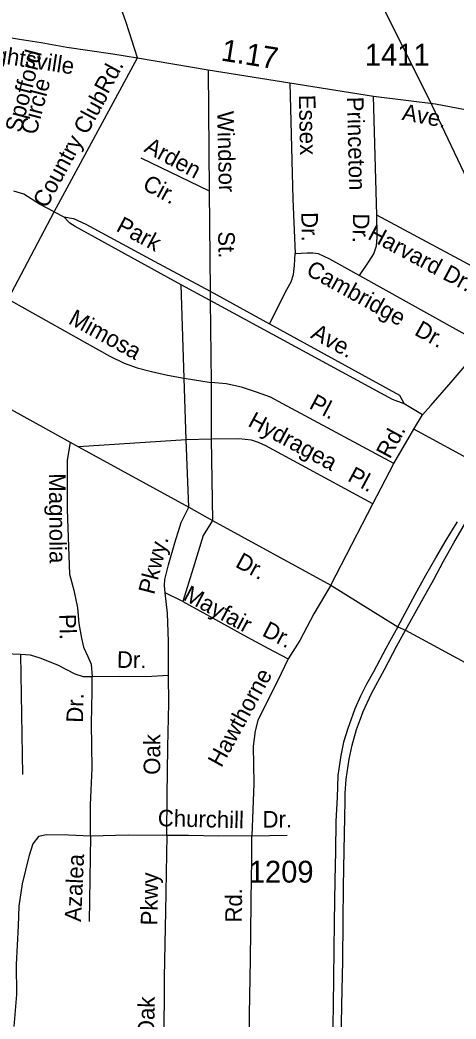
# Model space of a CAD drawing. Extents: x 2290055 to 2389491, y 66597 to 237875.
# Drawn here: x 2328196 to 2330699, y 169694 to 175420 of the extents above; entities that cross this region are included whole.
import ezdxf

# ---------------------------------------------------------------- set-up
doc = ezdxf.new("R2010")
doc.units = 0
for name, color, linetype in [('Exist Road Non-System Type 51', 7, 'Continuous'), ('Exist Road Non-System Type 51 Label', 7, 'Continuous'), ('Exist Road Primary US Label', 7, 'Continuous'), ('Exist Road Primary US UnDivided 4 Lane Attributed', 7, 'Continuous'), ('Exist Road Secondary Mileage Hundredths English Label', 7, 'Continuous'), ('Exist Road Secondary Type 51 Attributed', 7, 'Continuous'), ('Exist Road Secondary Type 51 Divided Attributed', 7, 'Continuous'), ('Exist Road Secondary Type 51 Label', 7, 'Continuous'), ('Exist Road Secondary Type 51 Number Label', 7, 'Continuous')]:
    doc.layers.add(name, color=color, linetype=linetype)

msp = doc.modelspace()

# ---------------------------------------------------------------- linework, layer by layer
at = {"layer": 'Exist Road Non-System Type 51'}
for p, q in [((2330561.4, 174929.9), (2330257.1, 175546)), ((2328392.9, 174319.9), (2328871.9, 175203)), ((2329277, 175135.1), (2329282.6, 174441.1)), ((2330244.3, 174301), (2330225.2, 174982.6)), ((2330818.7, 174392), (2330561.4, 174929.9)), ((2329282.6, 174441.1), (2329287.2, 173865)), ((2328128.5, 173819.2), (2328392.9, 174319.9)), ((2328392.9, 174319.9), (2328447.8, 174291.9)), ((2330822.7, 173991.8), (2330244.3, 174301)), ((2330145.8, 173955.1), (2330814.9, 173583.5)), ((2329287.3, 173813.2), (2329121.6, 173902.4)), ((2329138.9, 173367.2), (2329121.6, 173902.4)), ((2329287.2, 173865), (2329287.3, 173813.2)), ((2329287.2, 173865), (2329628.7, 173678.7)), ((2329287.3, 173813.2), (2329293.7, 173343.1)), ((2329138.9, 173367.2), (2329293.7, 173343.1)), ((2329150.9, 173013.5), (2329138.9, 173367.2)), ((2329293.7, 173343.1), (2329294.8, 173016.9)), ((2330507.6, 173157.2), (2330401, 173220.9)), ((2330456.7, 173075.1), (2330507.6, 173157.2)), ((2330342.7, 172878.6), (2330456.7, 173075.1)), ((2330896.4, 172836.5), (2330456.7, 173075.1)), ((2329150.9, 173013.5), (2328532.2, 172973)), ((2329294.8, 173016.9), (2329150.9, 173013.5)), ((2329166.2, 172627.9), (2329150.9, 173013.5)), ((2329294.8, 173016.9), (2329301.1, 172551.2)), ((2330221.5, 172647.6), (2330342.7, 172878.6)), ((2329980.1, 172179.9), (2330221.5, 172647.6)), ((2329131.5, 172086.3), (2329029.4, 172136.4)), ((2328199.3, 171783.2), (2328210.4, 171095.4)), ((2328600.5, 170741), (2328593.9, 170252.4)), ((2329526.6, 170743.5), (2329730.6, 170747.6))]:
    msp.add_line(p, q, dxfattribs=at)
for points in [[(2328871.9, 175203), (2328806.1, 175406.5), (2328718.2, 175653.2), (2328685.2, 175781.8)], [(2329746, 175059.8), (2329762.6, 174392.2), (2329776.8, 174082.6)], [(2328890.6, 174629.8), (2329282.6, 174441.1)], [(2328392.9, 174319.9), (2328309.1, 174364.5), (2328218.9, 174421), (2328160.8, 174438.6)], [(2329121.6, 173902.4), (2328514, 174236.5), (2328483.4, 174255.3), (2328447.8, 174291.9)], [(2328447.8, 174291.9), (2328504.3, 174282.4), (2328573.6, 174249), (2328966.2, 174038.4), (2329287.2, 173865)], [(2330145.8, 173955.1), (2330200.6, 174037.4), (2330226.8, 174080.4), (2330243.1, 174125.1), (2330247.1, 174173.1), (2330244.3, 174301)], [(2329776.8, 174082.6), (2329844.6, 174085.3), (2329876.8, 174084.6), (2329908.8, 174081.6), (2329974, 174050.4), (2330145.8, 173955.1)], [(2329628.7, 173678.7), (2329728.9, 173874.6), (2329753, 173919.6), (2329765.5, 173962.1), (2329771.4, 174012.2), (2329776.8, 174082.6)], [(2328128.5, 173819.2), (2328564.5, 173574.5), (2328711.5, 173494), (2328795.1, 173453.4), (2328868.4, 173426.4), (2328951.3, 173405.7), (2329044, 173383.5), (2329138.9, 173367.2)], [(2330401, 173220.9), (2330334.1, 173244.2), (2329287.3, 173813.2)], [(2329628.7, 173678.7), (2330375.1, 173270.1), (2330401, 173220.9)], [(2330507.6, 173157.2), (2330555.3, 173210.9), (2330672.1, 173343.9), (2330741.2, 173424.4), (2330765.9, 173453.6), (2330794.2, 173494.7), (2330806.8, 173533), (2330814.9, 173583.5)], [(2330342.7, 172878.6), (2329705, 173219.3), (2329635.1, 173258.5), (2329554.2, 173287.5), (2329468.8, 173315.9), (2329380.1, 173334.7), (2329293.7, 173343.1)], [(2328485.2, 173001), (2328467.4, 172894.3), (2328468.3, 172614.3), (2328476.8, 172348.5), (2328481, 172242.7), (2328504.7, 172151.4), (2328526.7, 172050.5), (2328534.2, 171960.6), (2328549.7, 171877.2), (2328561.5, 171825.8), (2328585.6, 171772.6), (2328605.5, 171727.4), (2328610.3, 171655.4)], [(2330221.5, 172647.6), (2329608.4, 172979.5), (2329565.7, 172997.8), (2329525.1, 173012.3), (2329452.6, 173019.2), (2329294.8, 173016.9)], [(2329029.4, 172136.4), (2329025.8, 172178.3), (2329028.4, 172212.2), (2329049, 172297), (2329086, 172422.5), (2329121.4, 172540.1), (2329166.2, 172627.9)], [(2329301.1, 172551.2), (2329248.4, 172465), (2329189.8, 172278.6), (2329131.5, 172086.3)], [(2329980.1, 172179.9), (2329882.6, 172015.9), (2329802.6, 171862.8), (2329736.5, 171758.1)], [(2329048.1, 171662.9), (2329048.7, 171856.9), (2329044.1, 172020.8), (2329029.4, 172136.4)], [(2329131.5, 172086.3), (2329266.4, 172011.5), (2329477.1, 171895.8), (2329618.3, 171819.4), (2329736.5, 171758.1)], [(2328199.3, 171783.2), (2328110.8, 171787.9), (2327942.6, 171791.1), (2327800.7, 171793.7), (2327668.1, 171802.2)], [(2328610.3, 171655.4), (2328560.4, 171655.7), (2328513.9, 171669.6), (2328413.7, 171721.8), (2328312, 171761.7), (2328257.2, 171779.6), (2328199.3, 171783.2)], [(2329736.5, 171758.1), (2329673.7, 171629.6), (2329599.4, 171482.5), (2329562.4, 171405.3), (2329546.7, 171346.5), (2329534.5, 171258.1), (2329539, 171044), (2329526.6, 170743.5)], [(2328600.5, 170741), (2328601.3, 170920.9), (2328611, 171131.3), (2328606.8, 171387.5), (2328611.6, 171571.4), (2328610.3, 171655.4)], [(2329048.1, 171662.9), (2328920.4, 171655.9), (2328766.4, 171657.6), (2328610.3, 171655.4)], [(2329038.5, 170746.2), (2329041.6, 170974.4), (2329044.4, 171252.5), (2329050.5, 171504.8), (2329048.1, 171662.9)], [(2328600.5, 170741), (2328474.2, 170747.8), (2328348.2, 170748.7), (2328302.6, 170739), (2328270.1, 170697.7), (2328247.1, 170624.9), (2328209.3, 170469.2), (2328190.1, 170340.4), (2328186.6, 170228.4), (2328175.4, 170005.7), (2328176.3, 169833.8), (2328161.6, 169651.1)], [(2329038.5, 170746.2), (2328818.2, 170747.3), (2328600.5, 170741)], [(2329038.5, 170746.2), (2329034.8, 170532), (2329031, 170310.8)], [(2329526.6, 170743.5), (2329336.6, 170741.9), (2329164.5, 170745.3), (2329038.5, 170746.2)], [(2329525.9, 170510.3), (2329526.8, 170589.6), (2329526.6, 170743.5)], [(2329512, 169546.6), (2329513.3, 169718.7), (2329518.9, 170035), (2329524.2, 170357.1), (2329525.9, 170510.3)], [(2329031, 170310.8), (2329029.4, 170219.7), (2329024.8, 169931.4), (2329021.8, 169551.2)]]:
    msp.add_lwpolyline(points, dxfattribs=at)
at = {"layer": 'Exist Road Primary US UnDivided 4 Lane Attributed'}
for points in [[(2325784, 174486.7), (2325904.3, 174417.4), (2326311.3, 174191.3), (2327128.8, 173753.7), (2327464.2, 173571), (2327877.6, 173335), (2328485.2, 173001), (2328532.2, 172973), (2329166.2, 172627.9), (2329301.1, 172551.2), (2329980.1, 172179.9), (2330364.4, 171942.5)], [(2330364.4, 171942.5), (2330409.6, 171923.1)], [(2330409.6, 171923.1), (2331391.7, 171391.3), (2332125.6, 171000.3), (2332755.3, 170655.3), (2333332.3, 170331.9), (2333399.2, 170306.7), (2333871.9, 170049), (2333973.9, 169991.1), (2334073.9, 169945.1), (2334225.2, 169863.2), (2334323.5, 169809), (2334394.9, 169769.8), (2334450.1, 169744.1), (2334506.8, 169722), (2334605.9, 169696.1), (2334954, 169649.8), (2335275.2, 169620.5), (2335810.1, 169555.7), (2336371.9, 169489.2), (2336574.6, 169464.8)]]:
    msp.add_lwpolyline(points, dxfattribs=at)
at = {"layer": 'Exist Road Secondary Type 51 Attributed'}
msp.add_lwpolyline([(2327541.4, 175415.8), (2327645.9, 175398.7), (2327843.2, 175364.5), (2328018.4, 175339.3), (2328193.5, 175310.4), (2328318.4, 175291.1), (2328465.4, 175265.1), (2328729.2, 175225.6), (2328871.9, 175203), (2329277, 175135.1), (2329746, 175059.8), (2330225.2, 174982.6), (2330581.7, 174939.6), (2330832.8, 174891.9), (2330953.4, 174851.3), (2331015.4, 174840.2), (2331061.4, 174832.3)], dxfattribs=at)
at = {"layer": 'Exist Road Secondary Type 51 Divided Attributed'}
for points in [[(2330409.6, 171923.1), (2330510.9, 172104.2), (2330571, 172212.1), (2330628.2, 172318.4), (2330686.2, 172423.4), (2330781.8, 172586.8), (2330871.6, 172729.5), (2330983.3, 172908.6), (2331043.8, 173010.8), (2331080.7, 173085.8), (2331109.5, 173159.6), (2331130.2, 173229.3), (2331145.4, 173304.8), (2331154.3, 173386.4), (2331156.8, 173469.5), (2331156.4, 173555.1), (2331154.7, 173625.1), (2331147.5, 173828.9), (2331141.2, 173989.3), (2331139.1, 174148.5), (2331135.3, 174346.1), (2331117.4, 174822.7)], [(2330364.4, 171942.5), (2330464.4, 172127), (2330526.1, 172237.6), (2330583, 172337.7), (2330642.7, 172438), (2330685.2, 172507.4), (2330708.3, 172543.4)], [(2330364.4, 171942.5), (2330316.9, 171855.1), (2330296.2, 171816.8), (2330224.8, 171684.3), (2330185.8, 171613.2), (2330150.4, 171545), (2330118.7, 171472.6), (2330106.2, 171438.9), (2330078.9, 171358.7), (2330053.8, 171280.5), (2330037.8, 171204.8), (2330020, 171088.8), (2330017.5, 170963.7), (2330009.7, 170828.3), (2330007.1, 170654.4), (2330004.5, 170490), (2330000.6, 170249.3), (2329998.4, 170088.4), (2329996.2, 169932.1), (2329993.2, 169769), (2329990.6, 169555.7)], [(2330040.2, 169546.2), (2330043.9, 169775.9), (2330048.7, 170024.8), (2330051.4, 170256.5), (2330053.5, 170451.7), (2330057.7, 170659.7), (2330063.1, 170944.2), (2330063.6, 170987.5), (2330068.4, 171068.8), (2330085.3, 171183.3), (2330102.3, 171264.4), (2330127.8, 171353), (2330150.6, 171414.6), (2330166, 171456.9), (2330214.8, 171558.9), (2330288, 171696.8), (2330358.6, 171832.1), (2330409.6, 171923.1)]]:
    msp.add_lwpolyline(points, dxfattribs=at)

# ---------------------------------------------------------------- texts
at = {"layer": 'Exist Road Non-System Type 51 Label'}
for s, rotation, p in [('Spofford', 75.3083, (2328201.4, 174770.2)), ('Rd.', 61.5246, (2328700.9, 174991.1)), ('Circle', 75.3083, (2328289.7, 174757.5)), ('Club', 61.5246, (2328581.5, 174757.3)), ('Essex', 271.1922, (2329796.9, 174990.4)), ('Princeton', 271.431, (2330073, 174978.9)), ('Windsor', 271.2925, (2329328.2, 174897.4)), ('Country', 61.5309, (2328348.7, 174336.1)), ('Arden', 331.762, (2328903.3, 174668.6)), ('Cir.', 331.762, (2328893.6, 174454.2)), ('Park', 331.7951, (2328742.8, 174214.1)), ('Dr.', 271.1922, (2329810.9, 174317.9)), ('Dr.', 269.1425, (2330107.8, 174312)), ('St.', 271.2638, (2329333.5, 174208.2)), ('Harvard Dr.', 331.8684, (2330186.8, 174168.2)), ('Cambridge', 330.9536, (2329832.4, 173964.2)), ('Mimosa', 331.2839, (2328468.8, 173683.1)), ('Dr.', 330.9536, (2330454.9, 173618.5)), ('Ave.', 331.3775, (2329859.7, 173601)), ('Pl.', 331.887, (2329850.6, 173197.2)), ('Hydragea', 331.5757, (2329499, 173095.4)), ('Rd.', 61.5906, (2330319.4, 172899.8)), ('Pl.', 331.5757, (2330071.1, 172781.2)), ('Magnolia', 270.3975, (2328363, 172821.3)), ('Pkwy.', 75.5087, (2328966.2, 172122.4)), ('Mayfair', 331.89, (2329127.5, 172099.4)), ('Pl.', 270.9831, (2328422.6, 172014.6)), ('Dr.', 332.6095, (2329580.9, 171894.1)), ('Dr.', 359.3372, (2328752.6, 171707)), ('Hawthorne', 61.2819, (2329352.4, 171130.7)), ('Dr.', 88.4872, (2328557.7, 171391.1)), ('Oak', 89.6107, (2329001.1, 171093.2)), ('Churchill', 358.5913, (2328986.7, 170799.2)), ('Dr.', 0.4859, (2329589.3, 170790.6)), ('Azalea', 87.355, (2328547, 170249.5)), ('Pkwy', 89.0869, (2328984.6, 170229.6)), ('Rd.', 89.2755, (2329469.5, 170246.1)), ('Oak', 89.0869, (2328966.9, 169588.5))]:
    msp.add_text(s, height=95, rotation=rotation, dxfattribs=at).set_placement(p)
at = {"layer": 'Exist Road Primary US Label'}
msp.add_text('Dr.', height=95, rotation=331.437, dxfattribs=at).set_placement((2329427, 172288.6))
at = {"layer": 'Exist Road Secondary Mileage Hundredths English Label'}
msp.add_text('1.17', height=125, rotation=350.8509, dxfattribs=at).set_placement((2329345.7, 175188.5))
at = {"layer": 'Exist Road Secondary Type 51 Label'}
for s, rotation, p in [('Wrightsville', 351.1897, (2327858.5, 175207.1)), ('Ave.', 349.2945, (2330385, 174848.1))]:
    msp.add_text(s, height=95, rotation=rotation, dxfattribs=at).set_placement(p)
at = {"layer": 'Exist Road Secondary Type 51 Number Label'}
for s, p in [('1411', (2330175.8, 175158.6)), ('1209', (2329509.8, 170475.7))]:
    msp.add_text(s, height=125, dxfattribs=at).set_placement(p)

doc.saveas('drawing.dxf')
